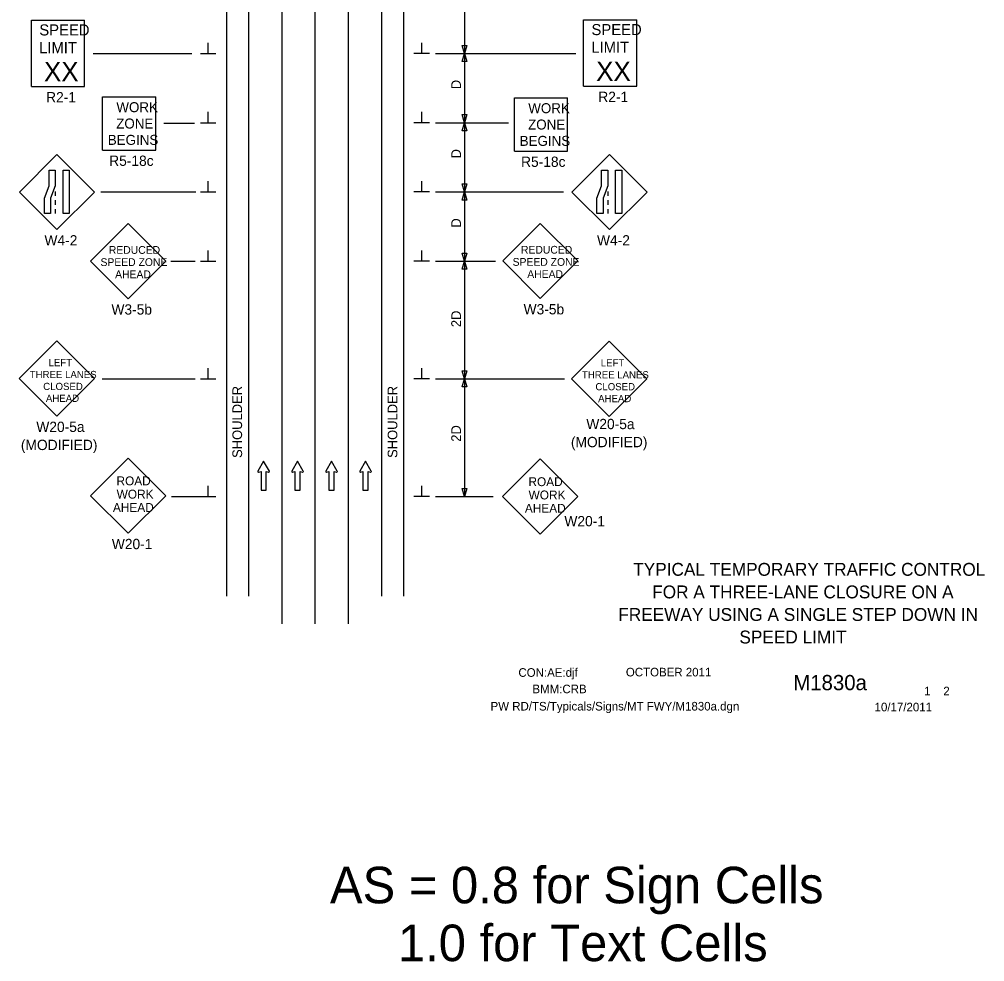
# Model space of a CAD drawing. Extents: x 16730 to 18479, y 5752 to 6927.
# Drawn here: x 16730 to 17427, y 5752 to 6433 of the extents above; entities that cross this region are included whole.
import ezdxf

# ---------------------------------------------------------------- set-up
doc = ezdxf.new("R2010")
doc.units = 0
for name, color, linetype in [('ALI_LEGAL_EX', 7, 'Continuous'), ('BORDER', 7, 'Continuous'), ('BORDER_SIGNAL_WO', 7, 'Continuous'), ('MT_SCRATCH_LEVEL_E', 7, 'Continuous'), ('PAVT_EDGE_EX', 7, 'Continuous'), ('TRAFFIC_SIGNS_PR', 7, 'Continuous'), ('TYPICAL_TEXT_DIMEN_PR', 7, 'Continuous')]:
    doc.layers.add(name, color=color, linetype=linetype)

msp = doc.modelspace()

# ---------------------------------------------------------------- linework, layer by layer
at = {"layer": 'ALI_LEGAL_EX'}
for p, q in [((16919.74, 6876.43), (16919.74, 5996.39)), ((16943.74, 6876.43), (16943.74, 5996.39)), ((16967.74, 6876.43), (16967.74, 5996.39))]:
    msp.add_line(p, q, dxfattribs=at)
for points in [[(16919.74, 6396.46), (16919.74, 6371.46)], [(16943.74, 6396.46), (16943.74, 6371.46)], [(16967.74, 6396.46), (16967.74, 6371.46)], [(16919.74, 6246.46), (16919.74, 6221.46)], [(16943.74, 6246.46), (16943.74, 6221.46)], [(16967.74, 6246.46), (16967.74, 6221.46)], [(16919.74, 6146.46), (16919.74, 6121.46)], [(16943.74, 6146.46), (16943.74, 6121.46)], [(16967.74, 6146.46), (16967.74, 6121.46)], [(16919.74, 6046.46), (16919.74, 6021.46)], [(16943.74, 6046.46), (16943.74, 6021.46)], [(16967.74, 6046.46), (16967.74, 6021.46)]]:
    msp.add_lwpolyline(points, dxfattribs=at)
at = {"layer": 'MT_SCRATCH_LEVEL_E'}
for p, q in [((16906.65, 6113.86), (16902.54, 6106.62)), ((16910.79, 6106.62), (16906.65, 6113.86)), ((16931.18, 6113.86), (16927.06, 6106.62)), ((16935.32, 6106.62), (16931.18, 6113.86)), ((16955.7, 6113.86), (16951.59, 6106.62)), ((16959.85, 6106.62), (16955.7, 6113.86)), ((16980.26, 6113.86), (16976.15, 6106.62)), ((16984.41, 6106.62), (16980.26, 6113.86)), ((16903.02, 6105.94), (16904.79, 6106.25)), ((16904.79, 6106.25), (16904.79, 6092.99)), ((16908.54, 6092.99), (16908.54, 6106.25)), ((16908.54, 6106.25), (16910.31, 6105.94)), ((16927.55, 6105.94), (16929.32, 6106.25)), ((16929.32, 6106.25), (16929.32, 6092.99)), ((16933.07, 6092.99), (16933.07, 6106.25)), ((16933.07, 6106.25), (16934.84, 6105.94)), ((16952.08, 6105.94), (16953.85, 6106.25)), ((16953.85, 6106.25), (16953.85, 6092.99)), ((16957.59, 6092.99), (16957.59, 6106.25)), ((16957.59, 6106.25), (16959.37, 6105.94)), ((16976.63, 6105.94), (16978.41, 6106.25)), ((16978.41, 6106.25), (16978.41, 6092.99)), ((16982.15, 6092.99), (16982.15, 6106.25)), ((16982.15, 6106.25), (16983.93, 6105.94)), ((16904.79, 6092.99), (16908.54, 6092.99)), ((16929.32, 6092.99), (16933.07, 6092.99)), ((16953.85, 6092.99), (16957.59, 6092.99)), ((16978.41, 6092.99), (16982.15, 6092.99))]:
    msp.add_line(p, q, dxfattribs=at)
for centre, start, end in [((16902.94, 6106.39), 150.42484, 279.96381), ((16910.38, 6106.39), 260.03619, 29.77312), ((16927.47, 6106.39), 150.42484, 279.96381), ((16934.91, 6106.39), 260.03619, 29.77312), ((16952, 6106.39), 150.42484, 279.96381), ((16959.44, 6106.39), 260.03619, 29.77312), ((16976.56, 6106.39), 150.42484, 279.96381), ((16984, 6106.39), 260.03619, 29.77312)]:
    msp.add_arc(centre, 0.463, start, end, dxfattribs=at)
at = {"layer": 'PAVT_EDGE_EX'}
for p, q in [((16879.74, 6926.69), (16879.74, 6016.42)), ((16895.74, 6926.69), (16895.74, 6016.42)), ((16991.74, 6926.69), (16991.74, 6016.42)), ((17007.74, 6926.69), (17007.74, 6016.42))]:
    msp.add_line(p, q, dxfattribs=at)
at = {"layer": 'TRAFFIC_SIGNS_PR'}
for p, q in [((16738.9, 6432.47), (16777.3, 6432.47)), ((16738.9, 6384.47), (16738.9, 6432.47)), ((16777.3, 6384.47), (16777.3, 6432.47)), ((17137.72, 6432.72), (17176.12, 6432.72)), ((17137.72, 6384.72), (17137.72, 6432.72)), ((17176.12, 6384.72), (17176.12, 6432.72)), ((16738.9, 6384.47), (16777.3, 6384.47)), ((17137.72, 6384.72), (17176.12, 6384.72)), ((16790.31, 6338.54), (16790.31, 6376.94)), ((16790.31, 6376.94), (16828.71, 6376.94)), ((16828.71, 6338.54), (16828.71, 6376.94)), ((17087.79, 6337.82), (17087.79, 6376.22)), ((17087.79, 6376.22), (17126.19, 6376.22)), ((17126.19, 6337.82), (17126.19, 6376.22)), ((16790.31, 6338.54), (16828.71, 6338.54)), ((16757.41, 6335.36), (16730.26, 6308.21)), ((16784.57, 6308.21), (16757.41, 6335.36)), ((17087.79, 6337.82), (17126.19, 6337.82)), ((17156.48, 6335.36), (17129.33, 6308.21)), ((17183.64, 6308.21), (17156.48, 6335.36)), ((16730.26, 6308.21), (16757.41, 6281.06)), ((16756.17, 6308.7), (16756.17, 6305.5)), ((16757.41, 6281.06), (16784.57, 6308.21)), ((17129.33, 6308.21), (17156.48, 6281.06)), ((17155.24, 6308.7), (17155.24, 6305.5)), ((17156.48, 6281.06), (17183.64, 6308.21)), ((16756.17, 6302.3), (16756.17, 6299.1)), ((17155.24, 6302.3), (17155.24, 6299.1)), ((16756.17, 6295.9), (16756.17, 6292.7)), ((17155.24, 6295.9), (17155.24, 6292.7)), ((16808.8, 6285.44), (16781.65, 6258.29)), ((16835.95, 6258.29), (16808.8, 6285.44)), ((17106.47, 6285.59), (17079.32, 6258.44)), ((17133.62, 6258.44), (17106.47, 6285.59)), ((16781.65, 6258.29), (16808.8, 6231.14)), ((16808.8, 6231.14), (16835.95, 6258.29)), ((17079.32, 6258.44), (17106.47, 6231.28)), ((17106.47, 6231.28), (17133.62, 6258.44)), ((16757.35, 6200.64), (16730.2, 6173.49)), ((16784.51, 6173.49), (16757.35, 6200.64)), ((17156.19, 6200.44), (17129.04, 6173.29)), ((17183.35, 6173.29), (17156.19, 6200.44)), ((16730.2, 6173.49), (16757.35, 6146.33)), ((16757.35, 6146.33), (16784.51, 6173.49)), ((17129.04, 6173.29), (17156.19, 6146.14)), ((17156.19, 6146.14), (17183.35, 6173.29)), ((16808.86, 6116), (16781.71, 6088.85)), ((16836.02, 6088.85), (16808.86, 6116)), ((17106.39, 6115.41), (17079.23, 6088.26)), ((17133.54, 6088.26), (17106.39, 6115.41)), ((16781.71, 6088.85), (16808.86, 6061.7)), ((16808.86, 6061.7), (16836.02, 6088.85)), ((17079.23, 6088.26), (17106.39, 6061.1)), ((17106.39, 6061.1), (17133.54, 6088.26))]:
    msp.add_line(p, q, dxfattribs=at)
for points in [[(16756.17, 6323.95), (16756.17, 6312.76), (16752.82, 6303.88), (16752.82, 6292.7), (16748.33, 6292.7), (16748.33, 6303.88), (16751.67, 6312.76), (16751.67, 6323.95)], [(16766.3, 6323.95), (16766.3, 6292.7), (16761.81, 6292.7), (16761.81, 6323.95)], [(17155.24, 6323.95), (17155.24, 6312.76), (17151.89, 6303.88), (17151.89, 6292.7), (17147.4, 6292.7), (17147.4, 6303.88), (17150.74, 6312.76), (17150.74, 6323.95)], [(17165.37, 6323.95), (17165.37, 6292.7), (17160.88, 6292.7), (17160.88, 6323.95)]]:
    msp.add_lwpolyline(points, close=True, dxfattribs=at)
at = {"layer": 'TYPICAL_TEXT_DIMEN_PR'}
for p, q in [((17051.74, 6458.29), (17051.74, 6408.29)), ((16866.61, 6408.29), (16866.61, 6416.08)), ((17020.86, 6408.29), (17020.86, 6416.08)), ((16783.48, 6408.29), (16854.71, 6408.29)), ((16860.99, 6408.29), (16872.24, 6408.29)), ((17026.49, 6408.29), (17015.24, 6408.29)), ((17030.74, 6408.29), (17132.23, 6408.29)), ((17051.74, 6408.29), (17050.17, 6414.15)), ((17050.17, 6414.15), (17051.74, 6414.15)), ((17050.17, 6402.43), (17051.74, 6408.29)), ((17051.74, 6414.15), (17053.31, 6414.15)), ((17053.31, 6414.15), (17051.74, 6408.29)), ((17051.74, 6408.29), (17051.74, 6358.29)), ((17051.74, 6408.29), (17053.31, 6402.43)), ((17051.74, 6402.43), (17050.17, 6402.43)), ((17053.31, 6402.43), (17051.74, 6402.43)), ((16866.61, 6358.29), (16866.61, 6366.08)), ((17020.86, 6358.29), (17020.86, 6366.08)), ((17051.74, 6358.29), (17050.17, 6364.15)), ((17050.17, 6364.15), (17051.74, 6364.15)), ((17051.74, 6364.15), (17053.31, 6364.15)), ((17053.31, 6364.15), (17051.74, 6358.29)), ((16834.53, 6357.9), (16856.74, 6357.9)), ((16860.99, 6358.29), (16872.24, 6358.29)), ((17026.49, 6358.29), (17015.24, 6358.29)), ((17030.74, 6358.29), (17083.52, 6358.29)), ((17050.17, 6352.43), (17051.74, 6358.29)), ((17051.74, 6352.43), (17050.17, 6352.43)), ((17051.74, 6358.29), (17051.74, 6308.29)), ((17051.74, 6358.29), (17053.31, 6352.43)), ((17053.31, 6352.43), (17051.74, 6352.43)), ((16866.61, 6308.29), (16866.61, 6316.08)), ((17020.86, 6308.29), (17020.86, 6316.08)), ((17051.74, 6308.29), (17050.17, 6314.15)), ((17050.17, 6314.15), (17051.74, 6314.15)), ((17051.74, 6314.15), (17053.31, 6314.15)), ((17053.31, 6314.15), (17051.74, 6308.29)), ((16789.05, 6308.29), (16857.75, 6308.29)), ((16860.99, 6308.29), (16872.24, 6308.29)), ((17026.49, 6308.29), (17015.24, 6308.29)), ((17030.74, 6308.29), (17123.2, 6308.29)), ((17050.17, 6302.43), (17051.74, 6308.29)), ((17051.74, 6308.29), (17053.31, 6302.43)), ((17051.74, 6308.29), (17051.74, 6258.29)), ((17051.74, 6302.43), (17050.17, 6302.43)), ((17053.31, 6302.43), (17051.74, 6302.43)), ((16866.61, 6258.29), (16866.61, 6266.08)), ((17020.86, 6258.29), (17020.86, 6266.08)), ((17051.74, 6258.29), (17050.17, 6264.15)), ((17050.17, 6264.15), (17051.74, 6264.15)), ((17051.74, 6264.15), (17053.31, 6264.15)), ((17053.31, 6264.15), (17051.74, 6258.29)), ((16839.55, 6258.29), (16857.3, 6258.29)), ((16860.99, 6258.29), (16872.24, 6258.29)), ((17026.49, 6258.29), (17015.24, 6258.29)), ((17030.74, 6258.29), (17074.2, 6258.29)), ((17050.17, 6252.43), (17051.74, 6258.29)), ((17051.74, 6258.29), (17051.74, 6173.29)), ((17051.74, 6258.29), (17053.31, 6252.43)), ((17051.74, 6252.43), (17050.17, 6252.43)), ((17053.31, 6252.43), (17051.74, 6252.43)), ((16866.61, 6173.29), (16866.61, 6181.08)), ((17020.86, 6173.29), (17020.86, 6181.08)), ((17051.74, 6173.29), (17050.17, 6179.15)), ((17050.17, 6179.15), (17051.74, 6179.15)), ((17051.74, 6179.15), (17053.31, 6179.15)), ((17053.31, 6179.15), (17051.74, 6173.29)), ((16790.14, 6173.29), (16857.3, 6173.29)), ((16860.99, 6173.29), (16872.24, 6173.29)), ((17026.49, 6173.29), (17015.24, 6173.29)), ((17030.74, 6173.29), (17124.03, 6173.29)), ((17050.17, 6167.43), (17051.74, 6173.29)), ((17051.74, 6173.29), (17051.74, 6088.29)), ((17051.74, 6173.29), (17053.31, 6167.43)), ((17051.74, 6167.43), (17050.17, 6167.43)), ((17053.31, 6167.43), (17051.74, 6167.43)), ((16866.61, 6088.29), (16866.61, 6096.08)), ((17020.86, 6088.29), (17020.86, 6096.08)), ((17051.74, 6088.29), (17050.17, 6094.15)), ((17050.17, 6094.15), (17051.74, 6094.15)), ((17051.74, 6094.15), (17053.31, 6094.15)), ((17053.31, 6094.15), (17051.74, 6088.29)), ((16840.07, 6088.29), (16867.3, 6088.29)), ((16860.99, 6088.29), (16872.24, 6088.29)), ((17026.49, 6088.29), (17015.24, 6088.29)), ((17030.74, 6088.29), (17072.52, 6088.29))]:
    msp.add_line(p, q, dxfattribs=at)

# ---------------------------------------------------------------- texts
at = {"layer": 'BORDER'}
for s, p in [('TYPICAL TEMPORARY TRAFFIC CONTROL', (17173.6, 6031.02)), ('FOR A THREE-LANE CLOSURE ON A', (17187.3, 6014.72)), ('FREEWAY USING A SINGLE STEP DOWN IN ', (17162.8, 5998.42)), ('SPEED LIMIT', (17250.3, 5982.12))]:
    msp.add_text(s, height=9.3, dxfattribs=at).set_placement(p)
at = {"layer": 'BORDER_SIGNAL_WO'}
for s, height, p in [('CON:AE:djf  ', 6.2, (17090.69, 5958.06)), ('    OCTOBER 2011', 6.2, (17159.08, 5958.34)), ('    M1830a   ', 11, (17272.86, 5948.38)), ('BMM:CRB', 6.2, (17100.81, 5946.17)), (' 1    2 ', 6.2, (17381.45, 5944.7)), ('PW RD/TS/Typicals/Signs/MT FWY/M1830a.dgn      ', 6.2, (17070.55, 5933.71)), ('10/17/2011', 6.2, (17347.93, 5933.13)), ('AS = 0.8 for Sign Cells', 26.4241, (16954.57, 5794.42)), ('     1.0 for Text Cells', 26.4241, (16954.57, 5752.64))]:
    msp.add_text(s, height=height, dxfattribs=at).set_placement(p)
at = {"layer": 'TRAFFIC_SIGNS_PR'}
for s, height, p in [('SPEED', 8, (16744.66, 6421.33)), ('SPEED', 8, (17143.48, 6421.58)), ('LIMIT', 8, (16744.5, 6408.53)), ('LIMIT', 8, (17143.32, 6408.78)), ('XX', 14.031, (16748.01, 6388.23)), ('XX', 14.031, (17146.83, 6388.47)), ('R2-1', 7.44, (16749.57, 6373.03)), ('R2-1', 7.44, (17148.39, 6373.28)), ('WORK', 7.217, (16800.31, 6365.91)), ('WORK', 7.217, (17097.79, 6365.19)), ('ZONE', 7.217, (16800.19, 6354.1)), ('ZONE', 7.217, (17097.67, 6353.38)), ('BEGINS', 7.217, (16794.12, 6342.29)), ('BEGINS', 7.217, (17091.6, 6341.57)), ('R5-18c', 7.44, (16795.12, 6327.11)), ('R5-18c', 7.44, (17092.6, 6326.38)), ('W4-2', 7.44, (16748.37, 6269.62)), ('W4-2', 7.44, (17147.44, 6269.62)), ('REDUCED', 5.6, (16794.86, 6263.6)), ('REDUCED', 5.6, (17092.53, 6263.74)), ('SPEED ZONE', 5.6, (16788.85, 6254.8)), ('SPEED ZONE', 5.6, (17086.52, 6254.94)), ('AHEAD', 5.6, (16799.41, 6246)), ('AHEAD', 5.6, (17097.08, 6246.14)), ('W3-5b', 7.44, (16796.75, 6219.7)), ('W3-5b', 7.44, (17094.42, 6219.84)), ('LEFT', 5.2, (16751.3, 6182.42)), ('LEFT', 5.2, (17150.14, 6182.22)), ('THREE LANES', 5.2, (16737.74, 6173.82)), ('THREE LANES', 5.2, (17136.58, 6173.62)), ('CLOSED', 5.2, (16747.47, 6165.22)), ('CLOSED', 5.2, (17146.31, 6165.02)), ('AHEAD', 5.2, (16749.42, 6156.62)), ('AHEAD', 5.2, (17148.26, 6156.42)), ('W20-5a', 7.44, (17139.74, 6136.94)), ('W20-5a', 7.44, (16742.49, 6134.89)), ('(MODIFIED)', 7.44, (16731.35, 6121.85)), ('(MODIFIED)', 7.44, (17128.6, 6123.9)), ('ROAD', 6.4, (16800.4, 6096.38)), ('ROAD', 6.4, (17097.93, 6095.79)), ('WORK', 6.4, (16800.51, 6086.78)), ('WORK', 6.4, (17098.04, 6086.19)), ('AHEAD', 6.4, (16797.82, 6077.18)), ('AHEAD', 6.4, (17095.35, 6076.59)), ('W20-1', 7.44, (17123.89, 6066.78)), ('W20-1', 7.44, (16797.03, 6050.26))]:
    msp.add_text(s, height=height, dxfattribs=at).set_placement(p)
at = {"layer": 'TYPICAL_TEXT_DIMEN_PR'}
for s, p in [('D', (17049.18, 6382.51)), ('D', (17049.18, 6332.51)), ('D', (17049.18, 6282.51)), ('2D', (17049.18, 6210.64)), ('SHOULDER', (16891.11, 6116.16)), ('SHOULDER', (17003.25, 6116.16)), ('2D', (17049.18, 6127.85))]:
    msp.add_text(s, height=7, rotation=90, dxfattribs=at).set_placement(p)

doc.saveas('drawing.dxf')
